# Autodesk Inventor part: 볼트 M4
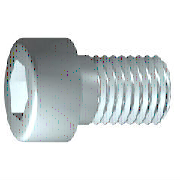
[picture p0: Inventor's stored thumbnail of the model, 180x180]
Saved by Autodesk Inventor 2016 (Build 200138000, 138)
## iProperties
IsCustomPart: 0
Created: 2012-02
Part Number: 볼트 M4
Material: 스테인리스강
Description: 6각 소켓 머리 캡 나사
Document SubType Name: Modeling
Standard: ISO 4762
Designer: mduedu
Standard Revision: Fourth edition 2004-03-01
Standards Organization: ISO
Language: ko-KR
Size Designation: M4 x 12
Categories: <MemberInstance><Categories><Category DisplayName="조임쇠" InternalName="e4da775c-781d-43d5-af7c-5136215cf5a6" Mnemonic="FSTN"><Category DisplayName="볼트" InternalN
Density: 8.08 g/cm^3
Appearance: 반광택
Author: mduedu
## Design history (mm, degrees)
sketch "스케치1"
  geometry: L1 (-1, 0)-(12, 0); L2 (12, 0)-(12, 2); L3 (12, 2)-(1.75, 2); L4 (1.75, 2)-(1.32, 2); L5 (1.32, 2)-(0, 2); L6 (0, 2)-(0, 3.5); L7 (0, 3.5)-(-4, 3.5); L8 (-4, 3.5)-(-4, 1.732); L9 (-4, 1.732)-(-2, 1.732); L10 (-2, 1.732)-(-1, 0); L11 (-7.2, 0)-(15.2, 0) reference; L12 (0, -0.7)-(0, 4.2) reference; L13 (1.75, 2)-(0, 2)
  constraints: 22 end point, 6 parallel, 2 collinear, 2 perpendicular, 1 horizontal, 1 point on line
  dimensions: "d1" = 10.25 distance from line of L3.end L2 (= GEL); "d2" = 0.42952 distance of L4.end L3.end (computed from GAL); "d3" = 4 distance between parallel lines of L8 L6 (= KOH); "d4" = 2 distance of L8.end L9.end (= INTI); "d5" = 60 deg angle of L10 L1; "d6" = 4 diameter of L3 L1 (= GD); "d7" = 4 diameter of L5 L1 (= BDM); "d8" = 3.4641 diameter of L9 L1 (= 1.1547 x SW); "d9" = 7 diameter of L7 L1 (= KOD); "d26" = 12 distance between parallel lines of L12 L2 (= NLG)
revolve "본체" sketch "스케치1" stored, may be unused: angle "d10" = 90 deg
sketch "스케치2"
  geometry: L1 (0, -4.9)-(0, 4.9) reference; L2 (-4.9, 0)-(4.9, 0) reference; L3 (1.732, 0)-(0.866, -1.5); L4 (0.866, -1.5)-(-0.866, -1.5); L5 (-0.866, -1.5)-(-1.732, 0); L6 (-1.732, 0)-(-0.866, 1.5); L7 (-0.866, 1.5)-(0.866, 1.5); L8 (0.866, 1.5)-(1.732, 0); 2 further points
  constraints: 12 end point, 1 coincident, 1 horizontal alignment, 1 point on line, 12 other
extrude "슬롯" join sketch "스케치2" stored distance "d11" = 10; taper "d12" = 0 deg
workplane "Work Plane1"
fillet "Fillet2" dims "d30" = 0.1 (= R)
body "Solid1"
fillet "모깎기1" dims "d17" = 0.4 (= RR)
feature "스레드" dims "d13" = 10.25 (= GEL), "d14" = 0
chamfer "모따기1" distance "d15" = 0.42941 (= -0.5 x SPD + 0.5 x GD); stored, may be unused: second distance "d16" = 0.42941 (= GUL), angle "d27" = 45 deg
other parameters: "GD" = 4 [user parameter; used in 2 equation terms], "NLG" = 12 [user parameter; used in 1 equation term], "GEL" = 10.25 [user parameter; used in 2 equation terms], "KOD" = 7 [user parameter; used in 1 equation term], "KOH" = 4 [user parameter; used in 1 equation term], "INTI" = 2 [user parameter; used in 1 equation term], "GAL" = 0.42941 (= 0.61345 x PTC) [user parameter; used in 1 equation term], "GUL" = 0.42941 (= 0.61345 x PTC) [user parameter; used in 1 equation term], "BDM" = 4 (= NND) [user parameter; used in 1 equation term], "SW" = 3 [user parameter; used in 2 equation terms], "RR" = 0.4 [user parameter; used in 1 equation term], "SPD" = 3.14117 (= NND - 1.2269 x PTC) [user parameter; used in 1 equation term], "d19" = 0, "d28" = 0, "d29" = 0, "R" = 0.1 [user parameter; used in 1 equation term], "TOA" = 30 deg [user parameter], "GD1" = 3.14117 (= THREADDIA - 1.2269 x PTC) [user parameter], "THREADDIA" = 4 [user parameter; used in 1 equation term], "FAWI" = 45 deg [user parameter], "TPU" = 14.28571 (computed from PTC) [user parameter], "PTC" = 0.7 [user parameter; used in 5 equation terms], "NND" = 4 [user parameter; used in 2 equation terms], "E0" = 3.465 (= 1.155 x SW) [user parameter]
